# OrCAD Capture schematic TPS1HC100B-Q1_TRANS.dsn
size B; title: TPS1HC100B-Q1, 100-mO, 2.5-A Single-Channel; rev: 1.0; note: Datasheet: SLVSFI1A     EVM: SLVUC30; note: High-Side Power Switch
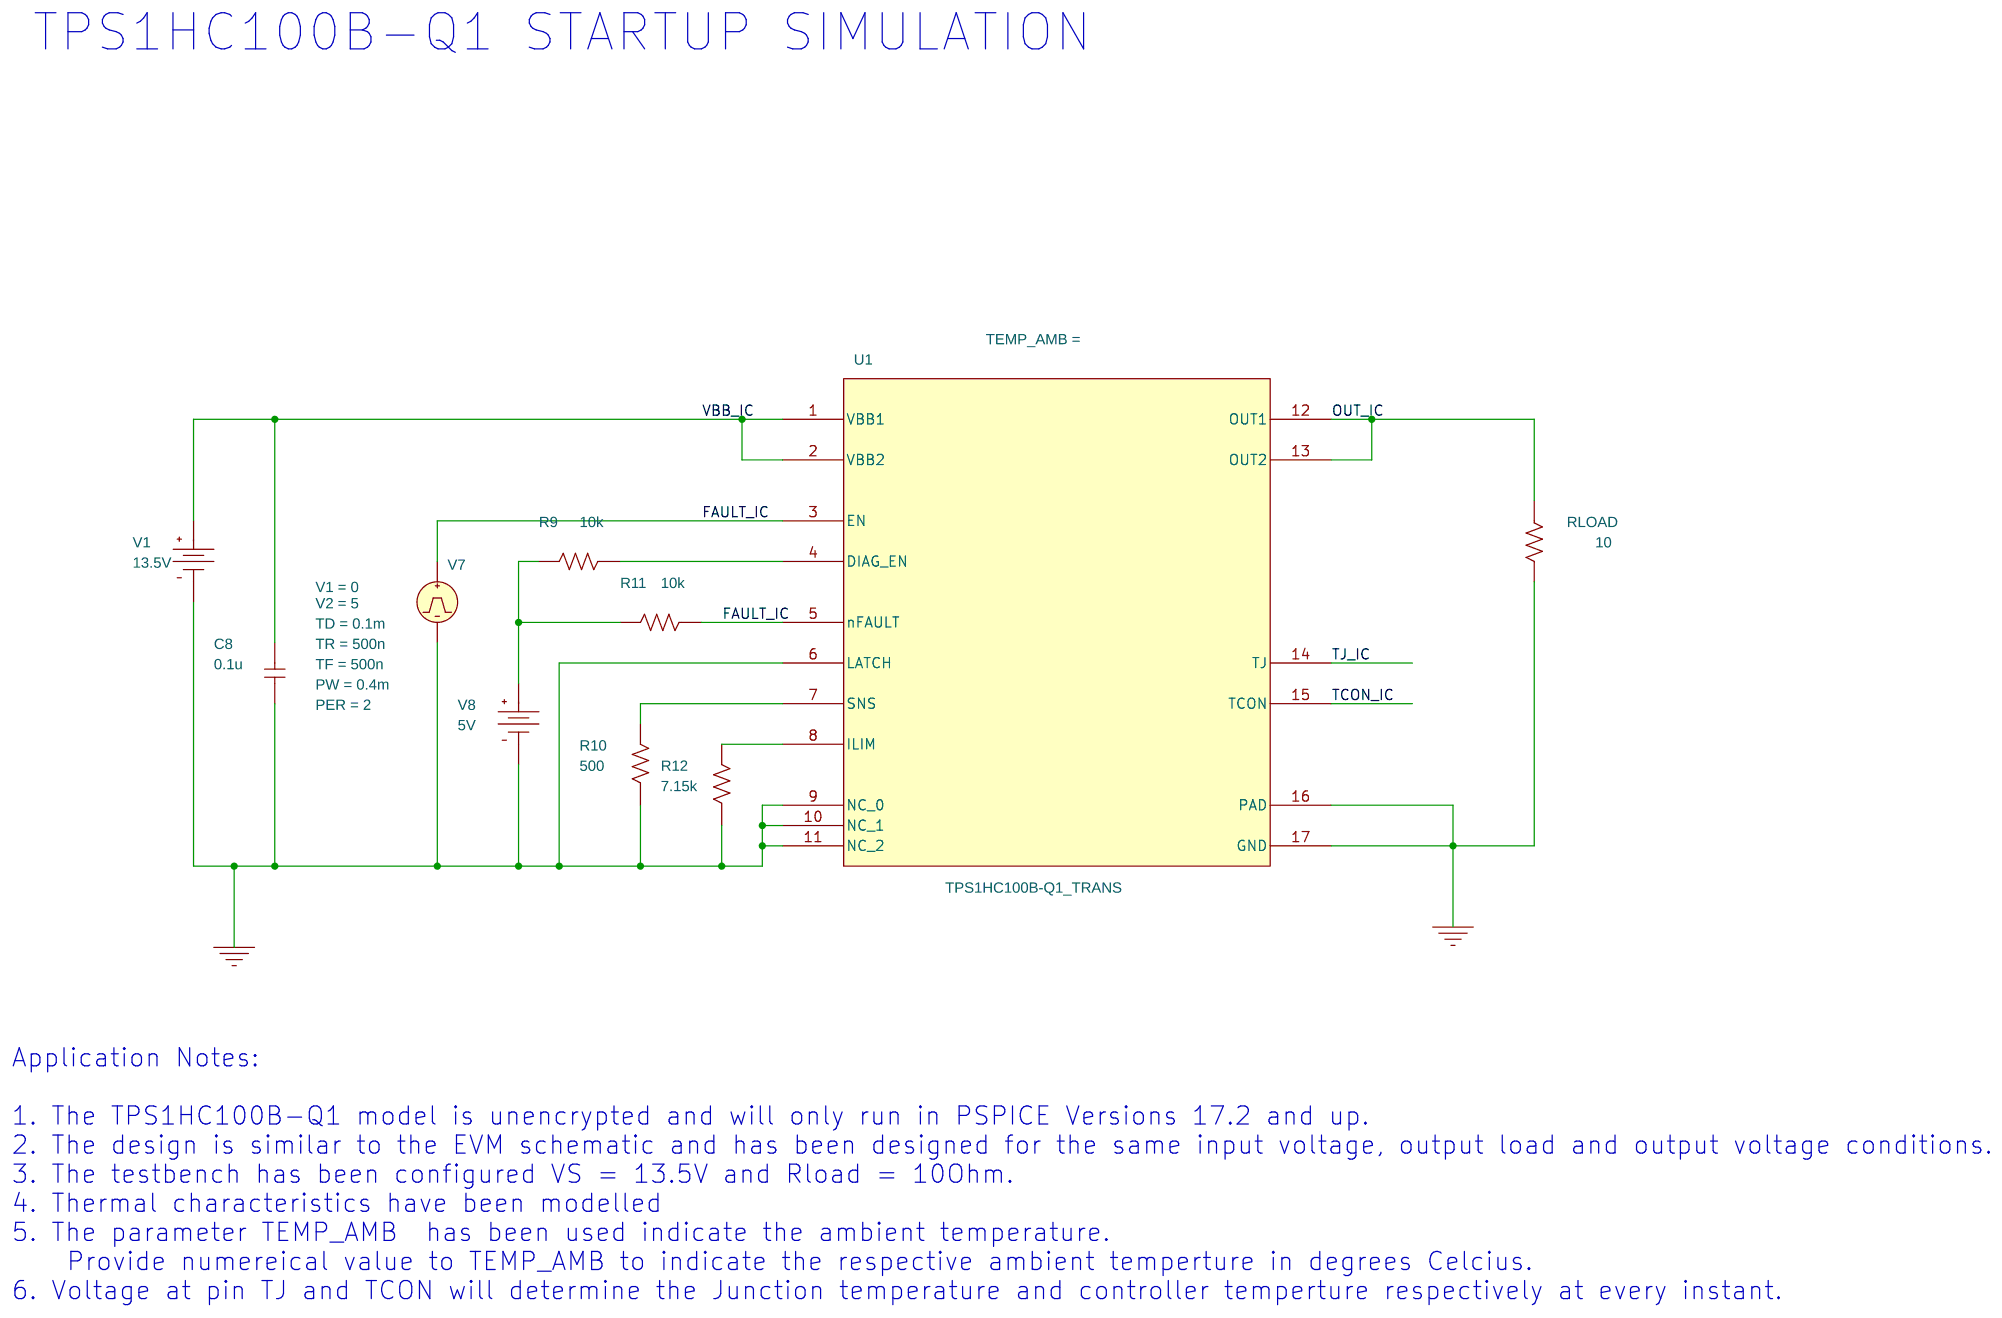
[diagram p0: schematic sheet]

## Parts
C8  0.1u  [RAD/CK05]
R9  10k  [AX/RC05]
R10  500  [AX/RC05]
R11  10k  [AX/RC05]
R12  7.15k  [AX/RC05]
RLOAD  10  [AX/RC05]
U1  TPS1HC100B-Q1_TRANS
V1  VDC
V7  VPULSE
V8  VDC

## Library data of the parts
C8 = C
R9-R12 RLOAD = R
U1 = TPS1HC100B-Q1_TRANS
V1 = VDC: DC: 13.5V
V7 = VPULSE: PER: 2; PW: 0.4m; TD: 0.1m; TF: 500n; TR: 500n; V1: 0; V2: 5
V8 = VDC: DC: 5V

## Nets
0: C8.1 R10.1 R12.1 RLOAD.2 U1.6(LATCH) U1.9(NC_0) U1.10(NC_1) U1.11(NC_2) U1.16(PAD) U1.17(GND) V1.1(-) V7.2(-) V8.1(-)
FAULT_IC: R11.1 U1.3(EN) U1.5(nFAULT) V7.1(+)
OUT_IC: RLOAD.1 U1.12(OUT1) U1.13(OUT2)
TCON_IC: U1.15(TCON)
TJ_IC: U1.14(TJ)
VBB_IC: C8.2 U1.1(VBB1) U1.2(VBB2) V1.0(+)
N16788072: R9.1 U1.4(DIAG_EN)
N16788079: R9.2 R11.2 V8.0(+)
N16788381: R12.2 U1.8(ILIM)
N16788384: R10.2 U1.7(SNS)

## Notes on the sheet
- TPS1HC100B-Q1 STARTUP SIMULATION
- Application Notes:
  1. The TPS1HC100B-Q1 model is unencrypted and will only run in PSPICE Versions 17.2 and up.
  2. The design is similar to the EVM schematic and has been designed for the same input voltage, output load and output voltage conditions.
  3. The testbench has been configured VS = 13.5V and Rload = 10Ohm.
  4. Thermal characteristics have been modelled
  5. The parameter TEMP_AMB  has been used indicate the ambient temperature.
      Provide numereical value to TEMP_AMB to indicate the respective ambient temperture in degrees Celcius.
  6. Voltage at pin TJ and TCON will determine the Junction temperature and controller temperture respectively at every instant.
